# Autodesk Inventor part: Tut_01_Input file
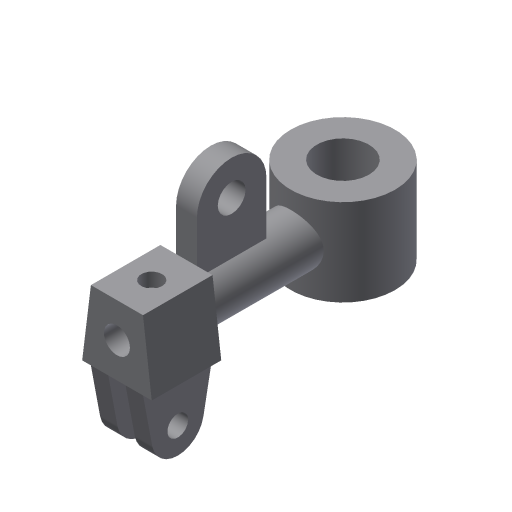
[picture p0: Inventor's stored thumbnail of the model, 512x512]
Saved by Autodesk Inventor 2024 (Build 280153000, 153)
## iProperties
Shininess: 77.0
Length Units: 11269
Angle Units: 11279
Time Units: 11290
Mass Units: 11283
Length Display Precision: 3
Angle Display Precision: 2
Created: 2001-12
Part Number: Tut_01_Input file
Document SubType Name: Modeling
Density: 1 g/cm^3
Material: Generic
Appearance: Default
Density: 0.0
Volumn: 0.0
Area: 0.0
PropertySet Name: Model Information
Control State: 0
Master: False
Checked Out: False
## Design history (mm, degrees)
sketch "Sketch1"
  geometry: C1 r 30 at (0, 0); 1 further point
  constraints: 1 centre point, 1 coincident, 1 other
  dimensions: "d0" = 60 diameter of C1
extrude "Extrusion1" new body sketch "Sketch1" stored distance "d1" = 50; taper "d2" = 0 deg
sketch "Sketch2"
  geometry: C1 r 15 at (0, 0); 1 further point
  constraints: 1 centre point, 1 coincident, 1 other
  dimensions: "d3" = 30 diameter of C1
extrude "Extrusion2" join sketch "Sketch2" distance "d4" = 130; taper "d5" = 0 deg
sketch "Sketch3"
  geometry: L1 (-15, 20)-(-20, -20); L2 (-20, -20)-(20, -20); L3 (20, -20)-(15, 20); L4 (15, 20)-(-15, 20); C1 r 15 at (0, 0) reference
  constraints: 8 end point, 1 equal length, 1 horizontal, 1 parallel
  dimensions: "d6" = 40 distance of L1.end L2.end; "d7" = 30 distance of L3.end L1.start; "d8" = 20 distance from line of C1.centre L4; "d9" = 40 distance between parallel lines of L4 L2; "d10" = 20 horizontal distance of C1.centre L2.end
extrude "Extrusion3" join sketch "Sketch3" distance "d11" = 40; taper "d12" = 0 deg
sketch "Sketch4"
  geometry: L1 (-90, 44)-(-90, 10.92); L2 (-90, 10.92)-(-50, 10.92); L3 (-50, 10.92)-(-50, 44); L4 (-90, 20)-(-90, -20) reference; L5 (-130, 20)-(-90, 20) reference; L6 (-90, -20)-(-90, 20) reference; C1 r 8 at (-70, 44); A1 r 20 centre (-70, 44) between (-50, 44) and (-90, 44); 1 further point
  constraints: 6 end point, 2 centre point, 2 point on circle, 2 tangent, 1 coincident, 1 midpoint, 1 parallel, 1 perpendicular, 1 point on line, 1 vertical
  dimensions: "d13" = 40 distance of L1.end L2.end; "d15" = 24 distance from line of L5 A1.centre; "d16" = 16 diameter of C1
extrude "Extrusion4" join sketch "Sketch4" stored distance "d17" = 12; taper "d18" = 0 deg
sketch "Sketch5"
  geometry: L1 (-130, -20)-(-124.738, -47.791); L2 (-95.262, -47.791)-(-90, -20); L3 (-90, -20)-(-130, -20); L4 (-130, -20)-(-90, -20) reference; L5 (-90, 20)-(-90, -20) reference; L6 (-130, 20)-(-130, -20) reference; L7 (-65.219, 30.926)-(-65.219, -115.614); L8 (-110, 38.032)-(-110, -78.704); C1 r 6 at (-110, -45); A1 r 15 centre (-110, -45) between (-124.738, -47.791) and (-95.262, -47.791)
  constraints: 10 end point, 3 point on line, 2 centre point, 2 collinear, 2 point on circle, 2 tangent, 2 vertical, 1 coincident, 1 horizontal
  dimensions: "d19" = 15 radius of A1; "d20" = 25 distance from line of L3 A1.centre; "d27" = 12 diameter of C1; "d53" = 20 distance between parallel lines of L6 L8
extrude "Extrusion5" join sketch "Sketch5" stored distance "d21" = 30; taper "d22" = 0 deg
sketch "Sketch6"
  geometry: L1 (-5, -20)-(5, -20); L2 (5, -20)-(5, -78.834); L3 (5, -78.834)-(-5, -78.834); L4 (-5, -78.834)-(-5, -20); L5 (-15, -20)-(15, -20) reference; L6 (15, -47.791)-(15, -20) reference
  constraints: 8 end point, 2 parallel, 1 collinear, 1 horizontal, 1 perpendicular
  dimensions: "d23" = 10 distance of L2.end L3.end; "d24" = 10 distance between parallel lines of L6 L2
extrude "Extrusion6" cut sketch "Sketch6" distance "d25" = 40; taper "d26" = 0 deg
sketch "Sketch7"
  geometry: 1 further point
hole "Hole1" sketch "Sketch7" at (0, 0) diameter "d28" = 15; stored, may be unused: countersink angle "d32" = 82 deg, drill point angle "d34" = 0 deg; dims "d29" = 6, "d30" = 4, "d31" = 2, "d33" = 110
sketch "Sketch8"
  geometry: L1 (30, 0)-(0, 0) reference; L2 (30, 0)-(30, 40) reference; 1 further point
  dimensions: "d35" = 20 distance from line of L1 point (15, 20); "d36" = 15 distance from line of L2 point (15, 20)
hole "Hole2" sketch "Sketch8" diameter "d37" = 12; stored, may be unused: countersink angle "d41" = 82 deg, drill point angle "d43" = 0 deg; dims "d38" = 6, "d39" = 4, "d40" = 2, "d42" = 8
sketch "Sketch9"
  geometry: C1 r 30 at (0, 0) reference
hole "Hole3" sketch "Sketch9" diameter "d44" = 30; stored, may be unused: countersink angle "d48" = 82 deg, drill point angle "d50" = 0 deg; dims "d45" = 6, "d46" = 4, "d47" = 2, "d49" = 8
body "Solid1"
